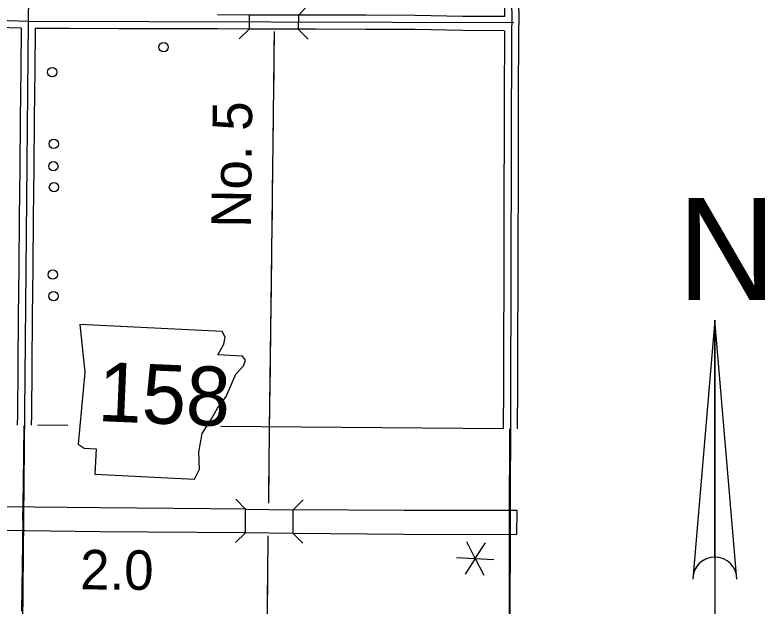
# Model space of a CAD drawing. Extents: x -4306 to 3843, y 131 to 8341.
# Drawn here: x 1424 to 2707, y 3423 to 4435 of the extents above; entities that cross this region are included whole.
import ezdxf

# ---------------------------------------------------------------- set-up
doc = ezdxf.new("R2010")
doc.units = 0
for name, color, linetype in [('10', 7, 'Continuous'), ('21', 7, 'Continuous'), ('32', 7, 'Continuous'), ('33', 7, 'Continuous'), ('34', 7, 'Continuous'), ('38', 7, 'Continuous'), ('50', 7, 'Continuous'), ('53', 7, 'Continuous'), ('56', 7, 'Continuous'), ('57', 7, 'Continuous'), ('61', 7, 'Continuous'), ('62', 7, 'Continuous')]:
    doc.layers.add(name, color=color, linetype=linetype)

msp = doc.modelspace()

# ---------------------------------------------------------------- linework, layer by layer
at = {"layer": '10'}
for p, q in [((1818.2, 3549.7), (1818.5, 3589.8)), ((1819.6, 3589.7), (1899.4, 3589)), ((1899.4, 3589), (1899.4, 3549)), ((2282.6, 3546.7), (2282.9, 3587.4)), ((1817.9, 3549.8), (1899.4, 3549))]:
    msp.add_line(p, q, dxfattribs=at)
for points in [[(1819.6, 3589.7), (1570.2, 3591.9), (1399.5, 3594.1), (1244.5, 3599.9)], [(2282.9, 3587.4), (2090.3, 3587.4), (1899.4, 3589)], [(1243, 3559.9), (1398.5, 3554.1), (1569.7, 3551.9), (1817.9, 3549.8)], [(1899.4, 3549), (2090.1, 3547.4), (2282.6, 3546.7)]]:
    msp.add_lwpolyline(points, dxfattribs=at)
at = {"layer": '21'}
msp.add_lwpolyline([(1535, 3905.7), (1543.2, 3824), (1531.8, 3701.2), (1542.3, 3693.9), (1562.6, 3693), (1560.5, 3649.7), (1730.8, 3641.4), (1739.8, 3658.5), (1738.5, 3687.1), (1744.1, 3719.3), (1760.2, 3744.3), (1770.6, 3762.7), (1785.1, 3782.4), (1794.3, 3803.6), (1801.9, 3820.8), (1814.8, 3835.1), (1818, 3844.4), (1812.9, 3851.5), (1771, 3853.5), (1781.4, 3872), (1783.3, 3884.1), (1778.2, 3893.7)], close=True, dxfattribs=at)
at = {"layer": '32'}
for p, q in [((1451.8, 4848.8), (1446.4, 4423.8)), ((2273.1, 4498.1), (2273.7, 4420.5)), ((2273.1, 4498.1), (2273.7, 4420.5)), ((2261.3, 4475.7), (2261.6, 4432)), ((2285.3, 4475.8), (2285.7, 4420.3)), ((1446.4, 4423.8), (1130.8, 4433)), ((1824.7, 4434.8), (1770.5, 4434.9)), ((1824.7, 4434.8), (1824.7, 4410.8)), ((1855, 4434.7), (1824.7, 4434.8)), ((1908.7, 4434.6), (1855, 4434.7)), ((1908.7, 4434.6), (1908.6, 4410.6)), ((1939.5, 4434.5), (1908.7, 4434.6)), ((2024, 4434.3), (1939.5, 4434.5)), ((2108.4, 4434), (2024, 4434.3)), ((2190.3, 4432.3), (2108.4, 4434)), ((2261.6, 4432), (2190.3, 4432.3)), ((1434.2, 4412.2), (1347.7, 4414.7)), ((1446.4, 4423.8), (1434.2, 3147)), ((2277.4, 4421.6), (1446.4, 4423.8)), ((2273.4, 4414.4), (2270.8, 3567.2)), ((2273.4, 4414.4), (2270.8, 3567.2)), ((2273.7, 4420.5), (2273.4, 4414.4)), ((2273.7, 4420.5), (2273.4, 4414.4)), ((2285.7, 4420.3), (2285.4, 4414.1)), ((1434.2, 4412.2), (1433.6, 4342)), ((1458.2, 4411.8), (1457.6, 4341.7)), ((1517, 4411.6), (1458.2, 4411.8)), ((1601.4, 4411.4), (1517, 4411.6)), ((1685.9, 4411.2), (1601.4, 4411.4)), ((1770.4, 4410.9), (1685.9, 4411.2)), ((1824.6, 4410.8), (1770.4, 4410.9)), ((1854.9, 4410.7), (1824.6, 4410.8)), ((1908.6, 4410.6), (1854.9, 4410.7)), ((1939.4, 4410.5), (1908.6, 4410.6)), ((2023.9, 4410.3), (1939.4, 4410.5)), ((2108.4, 4410), (2023.9, 4410.3)), ((2190.2, 4408.3), (2108.4, 4410)), ((2261.1, 4408), (2190.2, 4408.3)), ((2261.3, 4408), (2261.3, 4391.3)), ((2285.4, 4414.1), (2285.3, 4391.2)), ((2261.3, 4391.3), (2261, 4306.8)), ((2285.3, 4391.2), (2285, 4306.8)), ((1433.6, 4342), (1432.8, 4257.5)), ((1457.6, 4341.7), (1456.8, 4257.3)), ((2261, 4306.8), (2260.8, 4222.3)), ((2285, 4306.8), (2284.8, 4222.3)), ((1432.8, 4257.5), (1432, 4173)), ((1456.8, 4257.3), (1456, 4172.8)), ((2260.8, 4222.3), (2260.5, 4137.8)), ((2284.8, 4222.3), (2284.5, 4137.8)), ((1432, 4173), (1431.2, 4088.5)), ((1456, 4172.8), (1455.2, 4088.3)), ((2260.5, 4137.8), (2260.3, 4053.4)), ((2284.5, 4137.8), (2284.3, 4053.3)), ((1431.2, 4088.5), (1430.4, 4004)), ((1455.2, 4088.3), (1454.4, 4003.8)), ((2260.3, 4053.4), (2260, 3968.9)), ((2284.3, 4053.3), (2284, 3968.8)), ((1430.4, 4004), (1429.5, 3919.5)), ((1454.4, 4003.8), (1453.5, 3919.3)), ((2260, 3968.9), (2259.8, 3884.4)), ((2284, 3968.8), (2283.8, 3884.3)), ((1429.5, 3919.5), (1428.7, 3835.1)), ((1453.5, 3919.3), (1452.7, 3834.8)), ((2259.8, 3884.4), (2259.5, 3799.9)), ((2283.8, 3884.3), (2283.5, 3799.8)), ((1428.7, 3835.1), (1427.9, 3750.6)), ((1452.7, 3834.8), (1451.9, 3750.3)), ((2259.5, 3799.9), (2259.3, 3727.1)), ((2283.5, 3799.8), (2283.3, 3727.1)), ((1427.9, 3750.6), (1427.8, 3733.7)), ((1451.9, 3750.3), (1451.8, 3733.5)), ((2270.8, 3567.2), (2270, 3142.7)), ((2270.8, 3567.2), (2270, 3142.7))]:
    msp.add_line(p, q, dxfattribs=at)
at = {"layer": '33'}
for p, q in [((1438.2, 3634.3), (1439.7, 3732.3)), ((1437.5, 3570.3), (1438.2, 3634.3))]:
    msp.add_line(p, q, dxfattribs=at)
at = {"layer": '34'}
for p, q in [((2270.1, 3568.1), (2270.4, 3727.2)), ((1437.5, 3570.3), (1436.5, 3532.3)), ((2269.9, 3407.2), (2270.1, 3568.1)), ((1436.5, 3532.3), (1434.9, 3415.7))]:
    msp.add_line(p, q, dxfattribs=at)
at = {"layer": '38'}
for points in [[(1908.7, 4434.6), (1925.7, 4451.5)], [(1824.6, 4410.8), (1807.6, 4393.9)], [(1925.5, 4393.6), (1908.6, 4410.6)]]:
    msp.add_lwpolyline(points, dxfattribs=at)
at = {"layer": '50'}
for p, q in [((2621.3, 3913), (2584, 3476.8)), ((2621.3, 3913), (2621.3, 3315.6)), ((2621.3, 3508.2), (2621.3, 3913)), ((2584.5, 3482.8), (2586.2, 3484.5)), ((2584.7, 3485.2), (2588.2, 3488.6))]:
    msp.add_line(p, q, dxfattribs=at)
msp.add_lwpolyline([(2659.1, 3470.3), (2621.3, 3913), (2583.5, 3470.3)], dxfattribs=at)
for start, end in [(0, 180), (90, 170.2296)]:
    msp.add_arc((2621.3, 3470.3), 37.8, start, end, dxfattribs=at)
at = {"layer": '53'}
for points in [[(1514.1, 3733.1), (1462.5, 3733.5)], [(2259.3, 3727.3), (1776.1, 3731)]]:
    msp.add_lwpolyline(points, dxfattribs=at)
msp.add_lwpolyline([(2274.2, 3629.7), (2274.2, 3629.7), (2274.2, 3629.7)], close=True, dxfattribs=at)
at = {"layer": '56'}
for points in [[(1867.2, 4406.7), (1862.4, 3983.1), (1858.9, 3726.4), (1857.4, 3600.4)], [(1867.2, 4406.7), (1866.9, 4375)], [(1866.6, 4353.9), (1865.9, 4290.5)], [(1865.7, 4269.4), (1865, 4206)], [(1864.7, 4184.9), (1864, 4121.5)], [(1863.8, 4100.4), (1863, 4037)], [(1862.8, 4015.9), (1862.4, 3983.1), (1862, 3952.6)], [(1861.7, 3931.4), (1861.3, 3899.8)], [(1861.3, 3899.8), (1860.9, 3868.1)], [(1860.6, 3847), (1859.7, 3783.6)], [(1859.4, 3762.5), (1858.9, 3726.4), (1858.6, 3699.1)], [(1858.3, 3678), (1857.6, 3614.6)], [(1856.7, 3544.3), (1855.1, 3408.4), (1855.5, 3288.6), (1853.4, 3161.1)], [(1856.7, 3544.3), (1856.4, 3512.6)], [(1856.1, 3491.5), (1855.4, 3428.1)]]:
    msp.add_lwpolyline(points, dxfattribs=at)
at = {"layer": '57'}
for centre in [(1678.2, 4379.8), (1487.7, 4337.3), (1490.3, 4214.3), (1489.5, 4176.3), (1490.6, 4140.3), (1488.4, 3991), (1489.9, 3954.1)]:
    msp.add_circle(centre, 8, dxfattribs=at)
at = {"layer": '61'}
for p, q in [((2211.3, 3505.7), (2196.7, 3534.1)), ((2211.3, 3505.7), (2228.6, 3532.6)), ((2179.3, 3507.2), (2211.3, 3505.7)), ((2211.3, 3505.7), (2194, 3478.8)), ((2211.3, 3505.7), (2243.3, 3504.1)), ((2211.3, 3505.7), (2225.9, 3477.2))]:
    msp.add_line(p, q, dxfattribs=at)
at = {"layer": '62'}
for p, q in [((1818.4, 3569.7), (1818.4, 3569.7)), ((1899.6, 3569), (1899.6, 3569))]:
    msp.add_line(p, q, dxfattribs=at)
for points in [[(1818.5, 3589.8), (1801.7, 3606.9)], [(1916.9, 3605.9), (1899.7, 3589)], [(1801.1, 3532.9), (1818.2, 3549.7)], [(1899.4, 3549), (1916.2, 3531.9)]]:
    msp.add_lwpolyline(points, dxfattribs=at)

# ---------------------------------------------------------------- texts
at = {"layer": '21'}
msp.add_text('158', height=101.29, rotation=357.6004, dxfattribs=at).set_placement((1564.3, 3740.6))
at = {"layer": '50'}
msp.add_text('N', height=174.6, dxfattribs=at).set_placement((2557.5, 3947.3))
at = {"layer": '56'}
msp.add_text('No. 5', height=67.59, rotation=89.3217, dxfattribs=at).set_placement((1827.3, 4070.8))
at = {"layer": '61'}
msp.add_text('2.0', height=67.59, rotation=359.5003, dxfattribs=at).set_placement((1535.1, 3452.8))

doc.saveas('drawing.dxf')
